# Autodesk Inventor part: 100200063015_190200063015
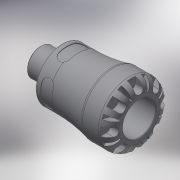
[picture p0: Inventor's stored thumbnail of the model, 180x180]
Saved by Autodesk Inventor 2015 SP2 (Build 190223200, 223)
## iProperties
Created: 2016-12
Part Number: 100200063015_190200063015
Material: Generic
Description: PLASSON MALE ADAPTOR 63X1.1/2" SERIES 1
Document SubType Name: Modeling
Designer: KIM
Mass: 447.839 g
Surface Area: 722.341 cm^2
Volume: 447.839 cm^3
Density: 1 g/cm^3
Appearance: Default
Author: KIM
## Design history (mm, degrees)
derived "1002.ipt"
feature "Solid1::1002.ipt"
tag "TaggingFeature1"
body "Solid1"
other parameters: "d0" = 125, "d1" = 38.64, "d2" = 63, "d3" = 78.75, "d4" = 103, "d6" = 92, "d8" = 87.55, "d13" = 9.7, "d14" = 9.7, "d15" = 0, "d17" = 360 deg, "d19" = 8 deg, "d20" = 1.26, "d21" = 1.26, "d22" = 8 deg, "d24" = 0, "d26" = 360 deg, "d32" = 0.925, "d33" = 10.3, "d34" = 47.803, "d35" = 12.6, "d38" = 19, "d39" = 1.43409, "d42" = 22.05, "d43" = 14.49, "d45" = 19.012, "d46" = 0, "d59" = 360 deg, "d61" = 18.7425, "d62" = 1.26, "d64" = 0, "d65" = 1.03, "d_" = 63, "E_" = 103, "H_" = 125, "l_" = 92, "R_" = 47.803, "l_2" = 19, "d9" = 12.125, "d11" = 103, "d12" = 78.75
